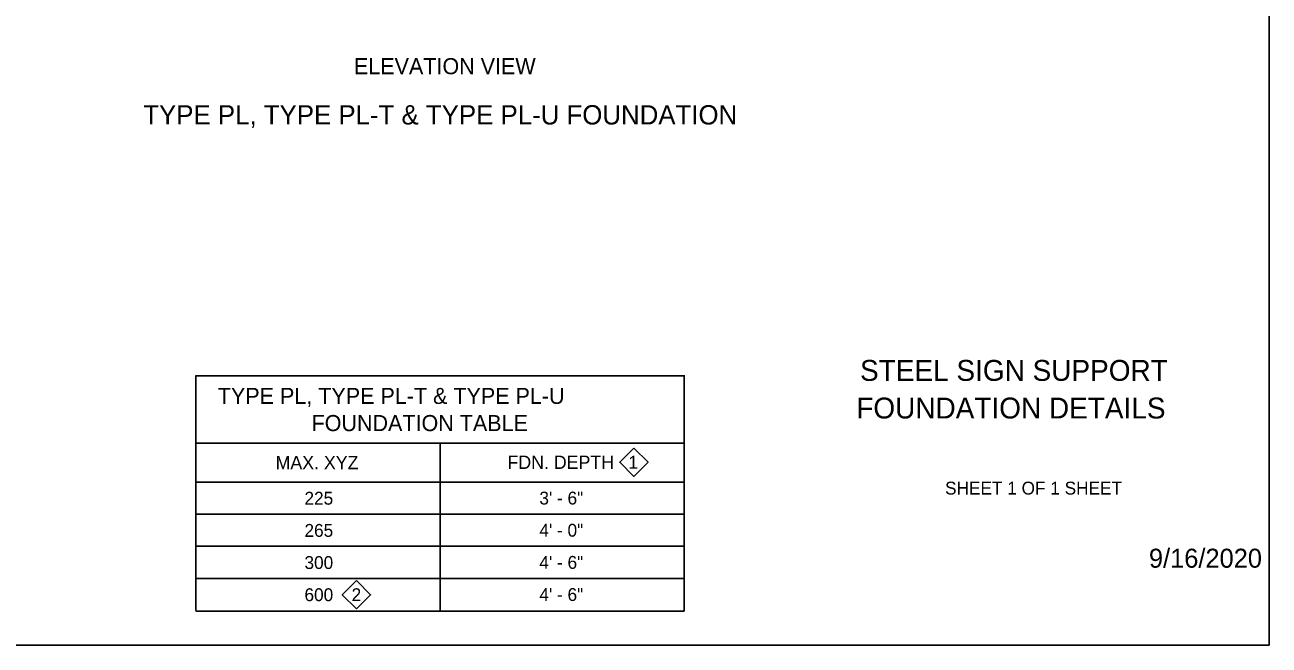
# Model space of a CAD drawing. Extents: x 99862 to 103151, y 102600 to 104676.
# Drawn here: x 101604 to 103151, y 102600 to 103371 of the extents above; entities that cross this region are included whole.
import ezdxf

# ---------------------------------------------------------------- set-up
doc = ezdxf.new("R2010")
doc.units = 0
for name, color, linetype in [('Level 1', 7, 'Continuous'), ('Level 15', 7, 'Continuous'), ('Level 20', 7, 'Continuous'), ('Level 40', 7, 'Continuous'), ('Level 62', 7, 'Continuous')]:
    doc.layers.add(name, color=color, linetype=linetype)

msp = doc.modelspace()

# ---------------------------------------------------------------- linework, layer by layer
at = {"layer": 'Level 1'}
msp.add_lwpolyline([(99862, 102599.5), (103151, 102599.5), (103151, 104675.5), (99862, 104675.5)], close=True, dxfattribs=at)
at = {"layer": 'Level 20'}
for points in [[(102361.5, 102844.5), (102379.1, 102827), (102361.5, 102809.4), (102343.9, 102827)], [(102016.5, 102679.8), (102034, 102662.2), (102016.5, 102644.7), (101998.9, 102662.2)]]:
    msp.add_lwpolyline(points, close=True, dxfattribs=at)
at = {"layer": 'Level 40'}
for p, q in [((101816.3, 102934.4), (102424.7, 102934.4)), ((101817, 102934.4), (101817, 102642.4)), ((102424, 102934.4), (102424, 102641.8)), ((101817, 102850.7), (102424, 102850.7)), ((102120.5, 102850.7), (102120.5, 102641.8)), ((101817, 102802.4), (102424, 102802.4)), ((101817, 102762.4), (102424, 102762.4)), ((101817, 102722.4), (102424, 102722.4)), ((101817, 102682.4), (102424, 102682.4)), ((101817, 102641.8), (102424, 102641.8))]:
    msp.add_line(p, q, dxfattribs=at)

# ---------------------------------------------------------------- texts
at = {"layer": 'Level 15'}
msp.add_text('9/16/2020', height=23.62, dxfattribs=at).set_placement((103001.6, 102695.8))
at = {"layer": 'Level 20'}
for s, height, p in [('ELEVATION VIEW', 20, (102013.4, 103309.6)), ('TYPE PL, TYPE PL-T & TYPE PL-U FOUNDATION', 24, (101751.5, 103247.1)), ('TYPE PL, TYPE PL-T & TYPE PL-U', 20, (101844.2, 102899.5)), ('FOUNDATION TABLE', 20, (101960.7, 102865.7)), ('FDN. DEPTH', 16.5, (102204.3, 102818.7)), ('1', 16, (102354.6, 102819)), ('2', 16, (102010.5, 102654.2))]:
    msp.add_text(s, height=height, dxfattribs=at).set_placement(p)
for s, height, p in [('MAX. XYZ', 16.5, (101916, 102818.3)), ('225', 16, (101951.9, 102774.2)), ('3\' - 6"', 16, (102243.9, 102774.4)), ('265', 16, (101951.9, 102734.2)), ('4\' - 0"', 16, (102243.9, 102734.4)), ('300', 16, (101951.9, 102694.2)), ('4\' - 6"', 16, (102243.9, 102694.4)), ('600', 16, (101951.9, 102654.2)), ('4\' - 6"', 16, (102243.9, 102654.4))]:
    msp.add_text(s, height=height, rotation=360, dxfattribs=at).set_placement(p)
at = {"layer": 'Level 62'}
for s, height, p in [('STEEL SIGN SUPPORT', 26, (102642.5, 102928.2)), ('FOUNDATION DETAILS', 26, (102637.8, 102881.4)), ('SHEET 1 OF 1 SHEET', 16, (102748.2, 102786.8))]:
    msp.add_text(s, height=height, dxfattribs=at).set_placement(p)

doc.saveas('drawing.dxf')
